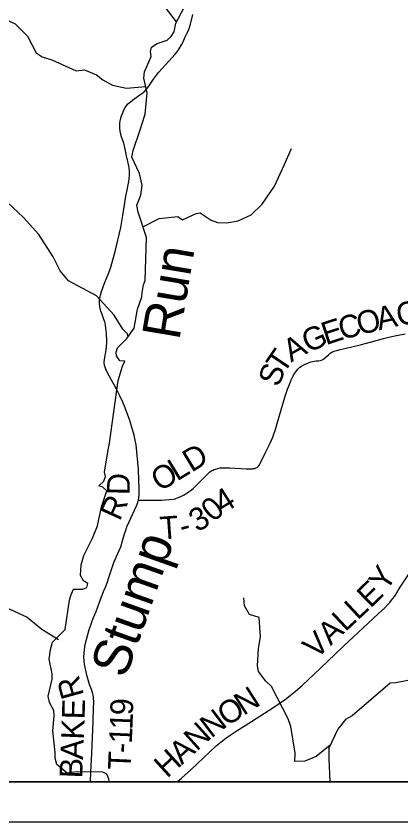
# Model space of a CAD drawing. Extents: x 0 to 34, y 0 to 22.
# Drawn here: x 4.796 to 5.757, y 14.3 to 16.31 of the extents above; entities that cross this region are included whole.
import ezdxf

# ---------------------------------------------------------------- set-up
doc = ezdxf.new("R2010")
doc.units = 0
for name, color, linetype in [('GM_X_County', 7, 'Continuous'), ('GM_X_County_Road', 7, 'Continuous'), ('GM_X_County_Road_Text', 7, 'Continuous'), ('GM_X_Minor_River', 7, 'Continuous'), ('GM_X_Minor_River_Text', 7, 'Continuous'), ('GM_X_Township', 7, 'Continuous'), ('GM_X_Township_Road', 7, 'Continuous'), ('GM_X_Township_Road_Text', 7, 'Continuous'), ('SH_Data', 7, 'Continuous')]:
    doc.layers.add(name, color=color, linetype=linetype)

msp = doc.modelspace()

# ---------------------------------------------------------------- linework, layer by layer
at = {"layer": 'GM_X_County'}
msp.add_lwpolyline([(7.0736, 21.2003), (2.6013, 21.2003), (2.6013, 14.4003), (9.4013, 14.4003), (9.4013, 21.1598)], dxfattribs=at)
at = {"layer": 'GM_X_County_Road'}
msp.add_lwpolyline([(5.199, 14.4003), (5.2088, 14.4088), (5.2323, 14.4298), (5.2799, 14.4747), (5.2959, 14.4891), (5.3079, 14.4995), (5.3195, 14.5083), (5.3308, 14.5163), (5.3457, 14.5257), (5.3839, 14.5505), (5.4395, 14.5862), (5.455, 14.5965), (5.4685, 14.606), (5.4803, 14.615), (5.4929, 14.6254), (5.5107, 14.6408), (5.5402, 14.668), (5.5916, 14.7175), (5.6142, 14.7392), (5.6746, 14.7957), (5.7004, 14.8194), (5.7162, 14.8341), (5.7231, 14.841), (5.729, 14.8474), (5.7359, 14.8559), (5.7413, 14.8631), (5.7551, 14.8851), (5.7795, 14.9228)], dxfattribs=at)
at = {"layer": 'GM_X_Minor_River'}
for points in [[(5.1964, 16.296), (5.161, 16.3423), (5.1537, 16.37), (5.1056, 16.4399), (5.0903, 16.4698), (5.0525, 16.5205), (5.0421, 16.5508), (5.0337, 16.5625), (4.998, 16.5848), (4.9755, 16.6082), (4.9216, 16.636), (4.9106, 16.6455), (4.8941, 16.6875), (4.8946, 16.7342), (4.8785, 16.7732), (4.8733, 16.8312), (4.871, 16.8411), (4.8645, 16.8566), (4.8655, 16.8706), (4.8723, 16.8832)], [(4.5528, 16.4798), (4.6319, 16.4163), (4.6702, 16.4031), (4.682, 16.3945), (4.7149, 16.3445), (4.7309, 16.3203), (4.7939, 16.291), (4.8248, 16.2604), (4.8466, 16.2184), (4.861, 16.2086), (4.8857, 16.2011), (4.9465, 16.1737), (4.9669, 16.1764), (4.9973, 16.1637), (5.0125, 16.1512), (5.0372, 16.138), (5.0721, 16.1306), (5.1199, 16.1343)], [(5.0677, 15.4492), (5.0552, 15.4499), (5.0468, 15.4624), (5.0457, 15.4719), (5.049, 15.4829), (5.0724, 15.5054), (5.0909, 15.5312), (5.099, 15.5791), (5.1098, 15.6095), (5.1109, 15.6201), (5.1146, 15.6399), (5.118, 15.6501), (5.1213, 15.7575), (5.1005, 15.8211), (5.0974, 15.8386), (5.1075, 15.8633), (5.1108, 15.8883), (5.1046, 15.9179), (5.0854, 15.958), (5.088, 15.9747), (5.106, 16.0264), (5.1108, 16.0424), (5.1187, 16.0652), (5.1234, 16.1187), (5.1152, 16.1554), (5.1163, 16.171), (5.1336, 16.2094), (5.1316, 16.2215), (5.1342, 16.2329), (5.1482, 16.2417), (5.1732, 16.2498), (5.1834, 16.2593), (5.1905, 16.2711), (5.1946, 16.2927), (5.216, 16.3319)], [(5.1124, 15.7847), (5.1532, 15.8054), (5.1998, 15.8106), (5.2116, 15.8019), (5.2457, 15.818), (5.2555, 15.8195), (5.2833, 15.8011), (5.2985, 15.7951), (5.3216, 15.7948), (5.3504, 15.7998), (5.3833, 15.814), (5.4101, 15.8407), (5.4409, 15.8863), (5.465, 15.938), (5.4833, 15.9802)], [(5.0759, 15.5103), (5.0739, 15.5171), (5.0628, 15.5292), (5.0407, 15.564), (4.9965, 15.612), (4.9273, 15.6497), (4.9063, 15.675), (4.8891, 15.7098), (4.8529, 15.7651), (4.8151, 15.8078), (4.7577, 15.8606), (4.7462, 15.8712)], [(5.0281, 14.4003), (5.0277, 14.407), (5.0231, 14.4188), (5.0128, 14.4241), (4.9484, 14.4249), (4.9234, 14.421), (4.8982, 14.4425), (4.894, 14.4588), (4.8939, 14.4725), (4.8883, 14.5271), (4.8916, 14.5647), (4.89, 14.5776), (4.8797, 14.5977), (4.8766, 14.6136), (4.8866, 14.6554), (4.8865, 14.6694), (4.8788, 14.7054), (4.8817, 14.7301), (4.8873, 14.748), (4.9186, 14.7796), (4.9292, 14.8529), (4.9329, 14.8643), (4.9393, 14.8802), (4.9628, 14.88), (4.9726, 14.8846), (4.9749, 14.8948), (4.9646, 14.9008), (4.9573, 14.9141), (4.9587, 14.9407), (4.9651, 14.9642), (4.9865, 15.0079), (4.9996, 15.038), (5.0092, 15.0854), (5.023, 15.1253), (5.0131, 15.1348), (5.0029, 15.1385), (5.015, 15.15), (5.0195, 15.1614), (5.0167, 15.1724), (5.0263, 15.2282), (5.0293, 15.2445), (5.0509, 15.4013), (5.0621, 15.4366), (5.0677, 15.4492)], [(4.588, 15.0161), (4.6123, 14.9392), (4.6477, 14.9135), (4.6561, 14.8874), (4.6626, 14.8764), (4.6918, 14.8769), (4.704, 14.8682), (4.7147, 14.8444), (4.7497, 14.8252), (4.7671, 14.8309), (4.7788, 14.8314), (4.824, 14.8107), (4.8606, 14.7805), (4.9024, 14.7549)], [(5.5804, 14.4911), (5.5448, 14.4632), (5.5168, 14.4509), (5.4918, 14.45), (5.4924, 14.4709), (5.4819, 14.5373), (5.4757, 14.557), (5.434, 14.6376), (5.4199, 14.6509), (5.4016, 14.6751), (5.3985, 14.6887), (5.4009, 14.732), (5.4061, 14.7616), (5.4032, 14.8098), (5.3789, 14.8173), (5.3659, 14.8388), (5.3643, 14.8586)], [(5.8769, 14.6726), (5.744, 14.647), (5.73, 14.6454), (5.6349, 14.5641), (5.6182, 14.5553), (5.5994, 14.531), (5.5769, 14.4838), (5.577, 14.4569), (5.5789, 14.4003)]]:
    msp.add_lwpolyline(points, dxfattribs=at)
at = {"layer": 'GM_X_Township'}
msp.add_lwpolyline([(2.6013, 16.5379), (2.6013, 14.4003), (6.0009, 14.4003)], dxfattribs=at)
at = {"layer": 'GM_X_Township_Road'}
for points in [[(5.1014, 15.1027), (5.1026, 15.1092), (5.1032, 15.1153), (5.1034, 15.1205), (5.1032, 15.1325), (5.1025, 15.1518), (5.1014, 15.1788), (5.0955, 15.2402), (5.0933, 15.252), (5.0906, 15.2647), (5.0843, 15.2872), (5.0793, 15.3038), (5.0728, 15.3215), (5.0683, 15.333), (5.0623, 15.347), (5.0549, 15.3629), (5.0469, 15.3793), (5.0412, 15.3902), (5.0345, 15.4018), (5.0228, 15.4238), (5.0193, 15.4315), (5.0179, 15.4357), (5.0171, 15.4385), (5.0166, 15.441), (5.0163, 15.4443), (5.0162, 15.4479), (5.0168, 15.4536), (5.0184, 15.4626), (5.0201, 15.4724), (5.0217, 15.484), (5.0228, 15.4964), (5.0225, 15.5056), (5.0221, 15.5118), (5.0217, 15.5183), (5.021, 15.5248), (5.0194, 15.5389), (5.0185, 15.5442), (5.0175, 15.5475), (5.0154, 15.5533), (5.0098, 15.5685), (5.0077, 15.5743), (5.0062, 15.5803), (5.0052, 15.5864), (5.0047, 15.5926), (5.0047, 15.5991), (5.0053, 15.6064), (5.0067, 15.6138), (5.0094, 15.623), (5.0126, 15.6321), (5.0169, 15.6437), (5.0228, 15.6581), (5.0274, 15.6696), (5.0325, 15.6842), (5.0378, 15.7021), (5.0432, 15.723), (5.0576, 15.7828), (5.0629, 15.8127), (5.0667, 15.8397), (5.0703, 15.8612), (5.0734, 15.8763), (5.0752, 15.8854), (5.0772, 15.8977), (5.0781, 15.9038), (5.079, 15.9124), (5.0793, 15.919), (5.079, 15.9253), (5.0784, 15.9306), (5.0773, 15.9357), (5.0749, 15.9472), (5.0719, 15.9617), (5.0687, 15.978), (5.0659, 15.9902), (5.065, 15.9934), (5.0596, 16.0092), (5.057, 16.0182), (5.0557, 16.0243), (5.0549, 16.0308), (5.0548, 16.0368), (5.0553, 16.0431), (5.0563, 16.0492), (5.0577, 16.0552), (5.0597, 16.0612), (5.0617, 16.0671), (5.0652, 16.0757), (5.068, 16.0812), (5.0714, 16.0864), (5.0733, 16.0888), (5.0754, 16.0911), (5.0776, 16.0933), (5.0823, 16.0974), (5.0898, 16.103), (5.105, 16.1137), (5.1126, 16.1191), (5.1172, 16.1232), (5.1214, 16.1278), (5.1272, 16.1351), (5.1394, 16.1531), (5.1466, 16.1632), (5.1524, 16.1705), (5.1605, 16.1799), (5.1775, 16.198), (5.186, 16.2071), (5.1921, 16.2141), (5.1979, 16.2213), (5.2034, 16.2288), (5.2089, 16.2383), (5.2132, 16.2463), (5.2185, 16.2585), (5.2219, 16.2653), (5.2254, 16.2729), (5.2288, 16.2817), (5.2313, 16.2904), (5.2371, 16.3145)], [(5.3243, 15.1833), (5.3298, 15.1832), (5.3705, 15.1806), (5.3798, 15.1805), (5.386, 15.1807), (5.3891, 15.1811), (5.3921, 15.1818), (5.3949, 15.1828), (5.3976, 15.1843), (5.4, 15.1862), (5.4021, 15.1884), (5.404, 15.1909), (5.4057, 15.1935), (5.4191, 15.2214), (5.4285, 15.2409), (5.4339, 15.2522), (5.437, 15.2595), (5.4395, 15.2667), (5.4435, 15.2784), (5.4479, 15.2933), (5.468, 15.3618), (5.4739, 15.3795), (5.4783, 15.3911), (5.4827, 15.4024), (5.4871, 15.4112), (5.4917, 15.4191), (5.4957, 15.4249), (5.4994, 15.4296), (5.5018, 15.4321), (5.504, 15.4341), (5.5085, 15.437), (5.5142, 15.4399), (5.5257, 15.4449), (5.532, 15.4473), (5.5361, 15.4485), (5.5401, 15.4492), (5.5452, 15.4499), (5.5507, 15.4504), (5.5554, 15.451), (5.5589, 15.4519), (5.5616, 15.4532), (5.5641, 15.4549), (5.5691, 15.4592), (5.5756, 15.4649), (5.5805, 15.4691), (5.5841, 15.4714), (5.5898, 15.4741), (5.5963, 15.4762), (5.6049, 15.4783), (5.6197, 15.4819), (5.6375, 15.4859), (5.6587, 15.4909), (5.6831, 15.4976), (5.7129, 15.5056), (5.7296, 15.5097), (5.7456, 15.513), (5.7676, 15.5171)], [(5.1014, 15.1027), (5.1156, 15.1025), (5.1468, 15.1021), (5.1597, 15.1028), (5.1783, 15.104), (5.1881, 15.1051), (5.1935, 15.1061), (5.2007, 15.1087), (5.2072, 15.1116), (5.2153, 15.1157), (5.2231, 15.1204), (5.2307, 15.1259), (5.2381, 15.1319), (5.2451, 15.1383), (5.2535, 15.1468), (5.2667, 15.16), (5.2752, 15.1688), (5.2799, 15.1728), (5.2851, 15.1762), (5.2879, 15.1776), (5.2907, 15.1789), (5.2936, 15.18), (5.2995, 15.1816), (5.3056, 15.1827), (5.3118, 15.1832), (5.3202, 15.1834), (5.3243, 15.1833)], [(4.9821, 14.4003), (4.9828, 14.4235), (4.9852, 14.47), (4.9884, 14.5507), (4.9898, 14.5851), (4.9899, 14.5977), (4.9893, 14.61), (4.9884, 14.6157), (4.9868, 14.6225), (4.9846, 14.6299), (4.9796, 14.6425), (4.976, 14.6539), (4.9727, 14.6657), (4.9692, 14.6813), (4.967, 14.6936), (4.9661, 14.7023), (4.9656, 14.7118), (4.9663, 14.721), (4.967, 14.7301), (4.969, 14.7422), (4.9717, 14.7549), (4.9789, 14.7796), (4.9834, 14.7933), (4.9859, 14.8011), (4.9874, 14.8046), (4.9898, 14.81), (4.9958, 14.8247), (5.004, 14.8482), (5.0134, 14.8719), (5.0145, 14.8745), (5.0197, 14.8856), (5.0237, 14.8959), (5.0287, 14.9116), (5.0363, 14.9348), (5.0414, 14.9491), (5.0433, 14.9538), (5.0463, 14.9604), (5.0574, 14.9857), (5.0592, 14.9906), (5.0613, 14.9983), (5.0638, 15.0068), (5.067, 15.0184), (5.0699, 15.0273), (5.0729, 15.0359), (5.0968, 15.0886), (5.0997, 15.0965), (5.1011, 15.1009), (5.1014, 15.1027)]]:
    msp.add_lwpolyline(points, dxfattribs=at)
at = {"layer": 'SH_Data'}
for p, q in [((2.6, 14.3997), (9.4, 14.3997)), ((2.5, 14.2997), (9.5, 14.2997))]:
    msp.add_line(p, q, dxfattribs=at)

# ---------------------------------------------------------------- texts
at = {"layer": 'GM_X_County_Road_Text'}
for s, rotation, p in [('Y', 57.3787, (5.7201, 14.8718)), ('E', 44.0841, (5.6804, 14.8311)), ('L', 43.1938, (5.6487, 14.8014)), ('L', 43.1909, (5.6178, 14.7723)), ('A', 43.1889, (5.5813, 14.7381)), ('V', 43.1914, (5.5449, 14.7038)), ('N', 32.7201, (5.3639, 14.5636)), ('O', 32.7939, (5.3219, 14.5365)), ('N', 37.1657, (5.283, 14.507)), ('N', 42.0571, (5.2469, 14.4743)), ('A', 42.1551, (5.2098, 14.4407)), ('H', 42.3849, (5.1729, 14.4071))]:
    msp.add_text(s, height=0.0568, rotation=rotation, dxfattribs=at).set_placement(p)
at = {"layer": 'GM_X_Minor_River_Text'}
for s, height, rotation, p in [('Run', 0.0947, 80.4431, (5.2034, 15.4995)), ('Stump', 0.09471, 70.4543, (5.069, 14.6552))]:
    msp.add_text(s, height=height, rotation=rotation, dxfattribs=at).set_placement(p)
at = {"layer": 'GM_X_Township_Road_Text'}
for s, rotation, p in [('A', 12.6217, (5.7019, 15.526)), ('C', 9.6035, (5.7499, 15.5368)), ('C', 14.7519, (5.6089, 15.5018)), ('O', 14.4391, (5.6539, 15.5137)), ('E', 18.0297, (5.5693, 15.4889)), ('G', 23.731, (5.5249, 15.4693)), ('A', 29.0518, (5.4825, 15.4456)), ('T', 55.9735, (5.4638, 15.4151)), ('S', 68.8144, (5.4515, 15.3824)), ('D', 31.213, (5.234, 15.1707)), ('L', 31.497, (5.1978, 15.1486)), ('O', 31.4941, (5.1551, 15.1224)), ('D', 88.7675, (5.0795, 15.1147)), ('4', 32.0285, (5.3129, 15.0674)), ('R', 65.5212, (5.0547, 15.0482)), ('0', 40.9211, (5.2884, 15.0459)), ('3', 29.9279, (5.2484, 15.0215)), ('T', 4.2423, (5.1572, 15.0041)), ('-', 15.3916, (5.2114, 15.0093)), ('R', 105.3499, (4.9662, 14.6157)), ('E', 88.4675, (4.9672, 14.5551)), ('9', 88.8367, (5.0879, 14.5654)), ('1', 87.5921, (5.0864, 14.5291)), ('K', 87.5962, (4.9651, 14.5042)), ('1', 87.5161, (5.0849, 14.494)), ('A', 87.5924, (4.963, 14.4542)), ('-', 87.4993, (5.0839, 14.4707)), ('T', 87.4965, (5.082, 14.4282)), ('B', 87.5911, (4.961, 14.4076))]:
    msp.add_text(s, height=0.0568, rotation=rotation, dxfattribs=at).set_placement(p)

doc.saveas('drawing.dxf')
